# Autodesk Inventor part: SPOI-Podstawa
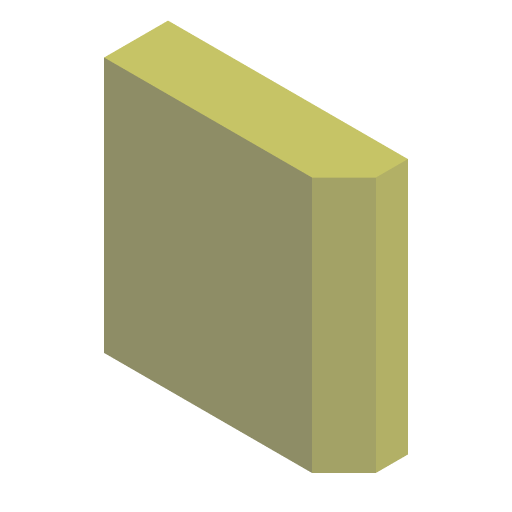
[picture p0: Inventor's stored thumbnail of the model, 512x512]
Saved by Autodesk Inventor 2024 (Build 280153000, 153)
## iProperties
Company: ATC
Shininess: 20.0
Length Units: 11269
Angle Units: 11279
Time Units: 11290
Mass Units: 11283
Length Display Precision: 3
Angle Display Precision: 2
Compacted: True
Created: 2023-03
Part Number: SPOI-Podstawa
Document SubType Name: Modeling
Designer: Andrzej Jaskulski
Material: Kurs-AJ
Density: 1 g/cm^3
Mass: 116 g
Surface Area: 176.314 cm^2
Volume: 116 cm^3
Appearance: Przezroczyste — żółte
Checked By: A.J.
Engr Approved By: Andrzej Jaskulski
Mfg Approved By: Andrzej Jaskulski
Authority: A.J.
Density: 0.0
Volumn: 0.0
Area: 0.0
PropertySet Name: Model Information
Control State: 0
Master: False
Checked Out: False
Title: A.J.: Kurs R2024-MEP
Author: Andrzej Jaskulski
Revision Number: 1/24
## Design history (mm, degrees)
node "Wyciągnięcie" dims "d4" = 20, "d5" = 0
node "Fazowanie1" dims "d6" = 10, "d7" = 10, "d42" = 45 deg
node "Bryła1"
node "Korpusy bryłowe"
node "Korpusy powierzchniowe"
sketch "Sketch1"
  geometry: L1 (-25, 55)-(-25, -25); L2 (50, 55)-(-25, 55); L3 (50, -25)-(50, 55); L4 (-25, -25)-(50, -25)
  constraints: 8 end point, 2 horizontal, 2 vertical, 1 other
  dimensions: "d1" = 80 distance of L3.start L2.start; "d3" = 75 distance of L2.start L1.start
other parameters: "d2" = 75 (derived), "d8" = 0, "d12" = 6.5 (derived), "d14" = 8.5 (derived), "d29" = 46 (derived), "d31" = 43 (derived), "d33" = 21.5 (derived), "d35" = 23 (derived), "d37" = 7.679 (derived)
